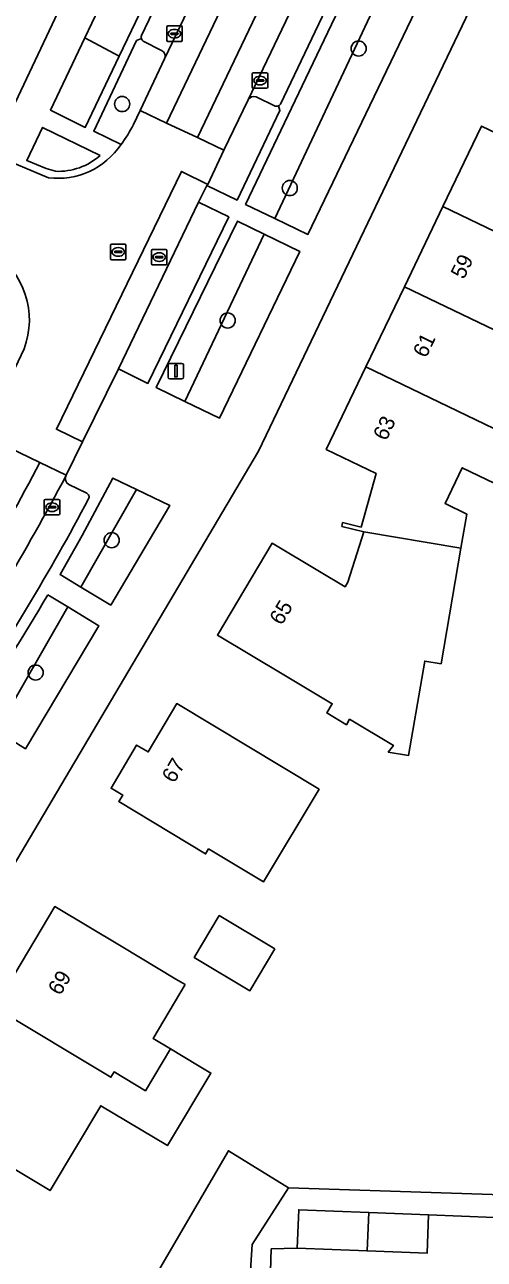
# Model space of a CAD drawing. Extents: x 161354 to 162026, y 386504 to 387460.
# Drawn here: x 161628.5 to 161658.2, y 386849.6 to 386929.5 of the extents above; entities that cross this region are included whole.
import ezdxf

# ---------------------------------------------------------------- set-up
doc = ezdxf.new("R2010")
doc.units = 0
for name, color, linetype in [('IMGEO_Boom', 7, 'Continuous'), ('IMGEO_Erf', 7, 'Continuous'), ('IMGEO_Groenvoorziening', 7, 'Continuous'), ('IMGEO_Kolk', 7, 'Continuous'), ('IMGEO_Lichtmast', 7, 'Continuous'), ('IMGEO_Pand', 7, 'Continuous'), ('IMGEO_Pand_nummerreeks', 7, 'Continuous'), ('IMGEO_Parkeervlak_open', 7, 'Continuous'), ('IMGEO_Rijbaan_lokaal_gesloten', 7, 'Continuous'), ('IMGEO_Rijbaan_lokaal_open', 7, 'Continuous'), ('IMGEO_Rioolput', 7, 'Continuous'), ('IMGEO_Voetpad_open', 7, 'Continuous')]:
    doc.layers.add(name, color=color, linetype=linetype)

msp = doc.modelspace()

# ---------------------------------------------------------------- linework, layer by layer
at = {"layer": 'IMGEO_Boom'}
for centre in [(161650.071, 386927.935), (161634.764, 386924.348), (161645.612, 386918.915), (161641.595, 386910.355), (161634.089, 386896.145), (161629.167, 386887.587)]:
    msp.add_circle(centre, 0.489, dxfattribs=at)
at = {"layer": 'IMGEO_Erf'}
for points in [[(161609.772, 386930.611), (161627.852, 386924.437), (161646.394, 386963.7)], [(161671.646, 386960.486), (161643.583, 386901.899), (161613.704, 386851.442), (161606.973, 386839.109)], [(161662.034, 386898.303), (161656.777, 386900.829), (161655.663, 386898.511), (161657.069, 386897.835), (161656.691, 386895.63), (161655.408, 386888.154), (161654.347, 386888.33), (161653.301, 386882.234), (161651.984, 386882.448), (161652.317, 386882.877), (161649.486, 386884.566), (161649.281, 386884.217), (161648.005, 386884.978), (161648.361, 386885.574), (161645.221, 386887.448), (161640.927, 386890.01), (161644.47, 386895.948), (161647.541, 386894.116), (161649.194, 386893.131), (161649.379, 386893.441), (161650.398, 386896.683), (161648.99, 386897.033), (161649.036, 386897.29), (161650.232, 386896.992), (161651.206, 386900.467), (161647.979, 386902.018), (161650.539, 386907.346), (161653.035, 386912.538), (161655.529, 386917.729), (161658.024, 386922.92), (161662.531, 386920.754)], [(161607.606, 386836.329), (161614.08, 386832.566), (161616.666, 386831.46), (161619.885, 386830.063), (161625.794, 386829.168), (161641.973, 386828.529), (161642.086, 386831.552), (161638.145, 386831.727), (161634.203, 386831.903), (161634.484, 386838.208), (161638.425, 386838.033), (161642.367, 386837.857), (161642.668, 386842.533), (161634.343, 386844.128), (161641.64, 386856.664), (161645.532, 386854.261), (161666.63, 386853.581)], [(161658.868, 386852.352), (161656.733, 386852.437), (161654.597, 386852.522), (161654.497, 386850.041), (161650.62, 386850.195), (161646.1, 386850.375), (161644.418, 386850.318), (161644.194, 386843.113), (161650.468, 386842.864), (161656.445, 386842.626), (161662.4, 386842.39)]]:
    msp.add_lwpolyline(points, dxfattribs=at)
for points in [[(161647.506, 386880.039), (161643.904, 386874.053), (161640.358, 386876.184), (161640.166, 386875.864), (161634.554, 386879.242), (161634.801, 386879.66), (161634.054, 386880.102), (161635.702, 386882.898), (161636.453, 386882.454), (161638.3, 386885.579)], [(161638.85, 386867.408), (161636.771, 386863.927), (161637.887, 386863.26), (161639.65, 386862.207), (161640.508, 386861.694), (161637.7, 386856.996), (161633.379, 386859.578), (161630.103, 386854.096), (161626.533, 386856.23), (161622.241, 386858.795), (161626.502, 386865.924), (161630.405, 386872.455), (161634.697, 386869.89), (161638.25, 386867.767)], [(161644.657, 386869.723), (161643.037, 386867.012), (161639.432, 386869.166), (161641.052, 386871.877)]]:
    msp.add_lwpolyline(points, close=True, dxfattribs=at)
at = {"layer": 'IMGEO_Groenvoorziening'}
for points in [[(161652.017, 386932.645), (161650.229, 386933.516), (161646.664, 386926.03), (161642.757, 386917.859), (161644.645, 386916.953)], [(161636.432, 386931.334), (161634.166, 386932.454), (161632.354, 386928.634), (161634.579, 386927.444)], [(161654.3, 386931.533), (161652.017, 386932.645), (161644.645, 386916.953), (161646.79, 386915.923)], [(161632.354, 386928.634), (161630.139, 386923.962), (161632.383, 386922.835), (161634.579, 386927.444)], [(161643.966, 386915.933), (161642.23, 386916.778), (161636.976, 386906.013), (161638.817, 386905.12)], [(161646.26, 386914.816), (161643.966, 386915.933), (161638.817, 386905.12), (161641.063, 386904.029)], [(161635.689, 386899.427), (161634.154, 386900.16), (161632.168, 386896.449), (161630.753, 386893.922), (161632.087, 386893.116)], [(161637.849, 386898.396), (161635.689, 386899.427), (161632.087, 386893.116), (161634.025, 386891.946)], [(161633.249, 386890.619), (161631.253, 386891.827), (161626.635, 386883.81), (161628.505, 386882.663)]]:
    msp.add_lwpolyline(points, close=True, dxfattribs=at)
for points in [[(161636.011, 386928.576), (161635.7, 386928.451), (161632.927, 386922.6), (161634.698, 386921.74)], [(161637.305, 386927.818), (161636.132, 386928.417)], [(161635.925, 386923.923), (161637.51, 386927.262)], [(161642.917, 386924.631), (161641.341, 386921.357), (161640.317, 386919.149), (161640.253, 386919.091), (161642.204, 386918.133), (161644.979, 386923.936), (161644.881, 386924.237)], [(161644.676, 386924.215), (161643.437, 386924.811)], [(161635.498, 386923.022), (161635.925, 386923.923)], [(161633.347, 386921.03), (161629.617, 386922.84), (161628.589, 386920.696)], [(161628.589, 386920.696), (161629.854, 386920.171), (161630.454, 386919.998)], [(161631.253, 386891.827), (161629.956, 386892.612)], [(161625.025, 386884.797), (161626.635, 386883.81), (161631.253, 386891.827)]]:
    msp.add_lwpolyline(points, dxfattribs=at)
for centre, radius, start, end in [((161636.286, 386928.66), 0.288, 196.9575, 237.58523), ((161637.133, 386927.439), 0.416, 334.85295, 65.62542), ((161643.303, 386924.356), 0.474, 73.59776, 144.58922), ((161644.744, 386924.547), 0.339, 258.40617, 293.84458), ((161627.063, 386927.395), 9.501, 323.47345, 332.59617), ((161630.631, 386924.072), 4.077, 267.50604, 311.75895), ((161490.613, 386975.069), 161.913, 326.11426, 329.38467)]:
    msp.add_arc(centre, radius, start, end, dxfattribs=at)
at = {"layer": 'IMGEO_Kolk'}
for p, q in [((161637.65, 386928.471), (161637.65, 386929.323)), ((161637.725, 386929.397), (161638.577, 386929.397)), ((161638.138, 386929.177), (161638.163, 386929.177)), ((161638.651, 386929.323), (161638.651, 386928.471)), ((161638.577, 386928.397), (161637.725, 386928.397)), ((161637.909, 386928.891), (161637.909, 386928.903)), ((161638.347, 386928.854), (161637.949, 386928.854)), ((161637.952, 386928.94), (161638.35, 386928.94)), ((161638.161, 386928.617), (161638.136, 386928.617)), ((161638.393, 386928.903), (161638.393, 386928.891)), ((161643.189, 386925.443), (161643.189, 386926.295)), ((161643.264, 386926.369), (161644.116, 386926.369)), ((161643.491, 386925.912), (161643.889, 386925.912)), ((161643.677, 386926.149), (161643.702, 386926.149)), ((161644.19, 386926.295), (161644.19, 386925.443)), ((161644.116, 386925.369), (161643.264, 386925.369)), ((161643.448, 386925.863), (161643.448, 386925.875)), ((161643.886, 386925.826), (161643.488, 386925.826)), ((161643.7, 386925.589), (161643.675, 386925.589)), ((161643.932, 386925.875), (161643.932, 386925.863)), ((161629.802, 386898.78), (161630.654, 386898.78)), ((161629.727, 386897.854), (161629.727, 386898.706)), ((161629.986, 386898.274), (161629.986, 386898.286)), ((161630.424, 386898.237), (161630.026, 386898.237)), ((161630.029, 386898.323), (161630.427, 386898.323)), ((161630.238, 386898), (161630.213, 386898)), ((161630.215, 386898.56), (161630.24, 386898.56)), ((161630.47, 386898.286), (161630.47, 386898.274)), ((161630.728, 386898.706), (161630.728, 386897.854)), ((161630.654, 386897.78), (161629.802, 386897.78))]:
    msp.add_line(p, q, dxfattribs=at)
for points in [[(161637.65, 386928.471), (161637.65, 386929.323)], [(161637.725, 386929.397), (161638.577, 386929.397)], [(161638.651, 386929.323), (161638.651, 386928.471)], [(161638.577, 386928.397), (161637.725, 386928.397)], [(161643.189, 386925.443), (161643.189, 386926.295)], [(161643.264, 386926.369), (161644.116, 386926.369)], [(161644.19, 386926.295), (161644.19, 386925.443)], [(161644.116, 386925.369), (161643.264, 386925.369)], [(161629.802, 386898.78), (161630.654, 386898.78)], [(161629.727, 386897.854), (161629.727, 386898.706)], [(161630.728, 386898.706), (161630.728, 386897.854)], [(161630.654, 386897.78), (161629.802, 386897.78)]]:
    msp.add_lwpolyline(points, dxfattribs=at)
for centre, radius, start, end in [((161637.727, 386929.321), 0.0765, 91.55205, 178.44795), ((161637.727, 386929.321), 0.0765, 91.55205, 178.44795), ((161638.575, 386929.321), 0.0765, 1.55205, 88.44795), ((161638.575, 386929.321), 0.0765, 1.55205, 88.44795), ((161637.727, 386928.473), 0.0765, 181.55205, 268.44795), ((161637.727, 386928.473), 0.0765, 181.55205, 268.44795), ((161637.949, 386928.9), 0.0403, 85.87752, 175.75265), ((161637.946, 386928.89), 0.0366, 178.93798, 274.71019), ((161638.35, 386928.897), 0.043, 264.86636, 352.45326), ((161638.354, 386928.902), 0.0386, 1.73085, 96.63898), ((161638.575, 386928.473), 0.0765, 271.55205, 358.44795), ((161638.575, 386928.473), 0.0765, 271.55205, 358.44795), ((161643.266, 386926.293), 0.0765, 91.55205, 178.44795), ((161643.266, 386926.293), 0.0765, 91.55205, 178.44795), ((161643.488, 386925.872), 0.0403, 85.87752, 175.75265), ((161643.893, 386925.874), 0.0386, 1.73085, 96.63898), ((161644.114, 386926.293), 0.0765, 1.55205, 88.44795), ((161644.114, 386926.293), 0.0765, 1.55205, 88.44795), ((161643.266, 386925.445), 0.0765, 181.55205, 268.44795), ((161643.266, 386925.445), 0.0765, 181.55205, 268.44795), ((161643.485, 386925.862), 0.0366, 178.93798, 274.71019), ((161643.889, 386925.869), 0.043, 264.86636, 352.45326), ((161644.114, 386925.445), 0.0765, 271.55205, 358.44795), ((161644.114, 386925.445), 0.0765, 271.55205, 358.44795), ((161629.804, 386898.704), 0.0765, 91.55205, 178.44795), ((161629.804, 386898.704), 0.0765, 91.55205, 178.44795), ((161630.652, 386898.704), 0.0765, 1.55205, 88.44795), ((161630.652, 386898.704), 0.0765, 1.55205, 88.44795), ((161630.026, 386898.283), 0.0403, 85.87752, 175.75265), ((161630.023, 386898.273), 0.0366, 178.93798, 274.71019), ((161630.427, 386898.28), 0.043, 264.86636, 352.45326), ((161630.431, 386898.285), 0.0386, 1.73085, 96.63898), ((161629.804, 386897.856), 0.0765, 181.55205, 268.44795), ((161629.804, 386897.856), 0.0765, 181.55205, 268.44795), ((161630.652, 386897.856), 0.0765, 271.55205, 358.44795), ((161630.652, 386897.856), 0.0765, 271.55205, 358.44795)]:
    msp.add_arc(centre, radius, start, end, dxfattribs=at)
for centre, major_axis, ratio, start_param, end_param in [((161638.137, 386928.897), (-0.387, 0.002), 0.722429, 4.712389, 7.853982), ((161638.162, 386928.897), (-0.39, 0.002), 0.717154, 1.570796, 4.712389), ((161643.676, 386925.869), (-0.387, 0.002), 0.722429, 4.712389, 7.853982), ((161643.701, 386925.869), (-0.39, 0.002), 0.717154, 1.570796, 4.712389), ((161630.214, 386898.28), (-0.387, 0.002), 0.722429, 4.712389, 7.853982), ((161630.239, 386898.28), (-0.39, 0.002), 0.717154, 1.570796, 4.712389)]:
    msp.add_ellipse(centre, major_axis=major_axis, ratio=ratio, start_param=start_param, end_param=end_param, dxfattribs=at)
at = {"layer": 'IMGEO_Lichtmast'}
for p, q in [((161637.847, 386907.579), (161638.637, 386907.579)), ((161638.637, 386907.579), (161637.847, 386907.579)), ((161637.747, 386906.679), (161637.747, 386907.479)), ((161637.747, 386907.479), (161637.747, 386906.679)), ((161638.737, 386907.479), (161638.737, 386906.679)), ((161638.737, 386906.679), (161638.737, 386907.479)), ((161638.637, 386906.579), (161637.847, 386906.579)), ((161637.847, 386906.579), (161638.637, 386906.579))]:
    msp.add_line(p, q, dxfattribs=at)
msp.add_lwpolyline([(161638.167, 386907.454), (161638.317, 386907.454), (161638.317, 386906.704), (161638.167, 386906.704), (161638.167, 386907.454)], dxfattribs=at)
for centre, start, end in [((161637.847, 386907.479), 90, 180), ((161637.847, 386907.479), 90, 180), ((161638.637, 386907.479), 0, 90), ((161638.637, 386907.479), 360, 90), ((161637.847, 386906.679), 180, 270), ((161637.847, 386906.679), 180, 270), ((161638.637, 386906.679), 270, 0), ((161638.637, 386906.679), 270, 0)]:
    msp.add_arc(centre, 0.1, start, end, dxfattribs=at)
at = {"layer": 'IMGEO_Pand'}
for points in [[(161666.552, 386916.092), (161667.619, 386918.309), (161666.003, 386919.086), (161662.531, 386920.754), (161658.024, 386922.92), (161655.529, 386917.729), (161667.953, 386911.758), (161671.703, 386910.095), (161673.808, 386909.162), (161673.944, 386909.444), (161674.115, 386909.362), (161674.884, 386910.962), (161673.53, 386911.613), (161673.959, 386912.504)], [(161667.953, 386911.758), (161655.529, 386917.729), (161653.035, 386912.538), (161661.001, 386908.709), (161662.248, 386911.305), (161666.867, 386909.031), (161666.627, 386908.543), (161670.128, 386906.819), (161670.364, 386907.309), (161670.387, 386907.356), (161670.821, 386908.26), (161671.703, 386910.095)], [(161659.915, 386906.45), (161661.001, 386908.709), (161653.035, 386912.538), (161650.539, 386907.346), (161662.985, 386901.364), (161663.411, 386901.166), (161664.69, 386903.828), (161664.817, 386904.094)], [(161663.411, 386901.166), (161662.985, 386901.364), (161650.539, 386907.346), (161647.979, 386902.018), (161651.206, 386900.467), (161650.232, 386896.992), (161649.036, 386897.29), (161648.99, 386897.033), (161650.398, 386896.683), (161656.691, 386895.63), (161657.069, 386897.835), (161655.663, 386898.511), (161656.777, 386900.829), (161662.034, 386898.303), (161662.155, 386898.553), (161662.359, 386898.977)], [(161656.691, 386895.63), (161650.398, 386896.683), (161649.379, 386893.441), (161649.194, 386893.131), (161647.541, 386894.116), (161644.47, 386895.948), (161640.927, 386890.01), (161645.221, 386887.448), (161648.361, 386885.574), (161648.005, 386884.978), (161649.281, 386884.217), (161649.486, 386884.566), (161652.317, 386882.877), (161651.984, 386882.448), (161653.301, 386882.234), (161654.347, 386888.33), (161655.408, 386888.154)], [(161636.453, 386882.454), (161635.702, 386882.898), (161634.054, 386880.102), (161634.801, 386879.66), (161634.554, 386879.242), (161640.166, 386875.864), (161640.358, 386876.184), (161643.904, 386874.053), (161647.506, 386880.039), (161638.3, 386885.579)], [(161638.85, 386867.408), (161638.25, 386867.767), (161634.697, 386869.89), (161630.405, 386872.455), (161626.502, 386865.924), (161634.037, 386861.419), (161634.242, 386861.762), (161636.267, 386860.551), (161637.887, 386863.26), (161636.771, 386863.927)], [(161644.657, 386869.723), (161641.052, 386871.877), (161639.432, 386869.166), (161643.037, 386867.012)], [(161626.502, 386865.924), (161622.241, 386858.795), (161626.533, 386856.23), (161630.103, 386854.096), (161633.379, 386859.578), (161637.7, 386856.996), (161640.508, 386861.694), (161639.65, 386862.207), (161637.887, 386863.26), (161636.267, 386860.551), (161634.242, 386861.762), (161634.037, 386861.419)], [(161645.532, 386854.261), (161641.64, 386856.664), (161634.343, 386844.128), (161642.668, 386842.533), (161643.19, 386850.602)], [(161650.72, 386852.676), (161646.198, 386852.856), (161646.1, 386850.375), (161650.62, 386850.195)], [(161654.597, 386852.522), (161650.72, 386852.676), (161650.62, 386850.195), (161654.497, 386850.041)]]:
    msp.add_lwpolyline(points, close=True, dxfattribs=at)
at = {"layer": 'IMGEO_Parkeervlak_open'}
for points in [[(161653.421, 386960.496), (161651.637, 386961.362), (161636.021, 386928.775)], [(161637.51, 386927.262), (161653.421, 386960.496)], [(161658.053, 386951.639), (161656.28, 386952.508), (161642.917, 386924.631)], [(161645.018, 386924.348), (161658.053, 386951.639)], [(161636.132, 386928.417), (161637.305, 386927.818)], [(161643.437, 386924.811), (161644.676, 386924.215)], [(161632.47, 386899.18), (161631.319, 386899.754)]]:
    msp.add_lwpolyline(points, dxfattribs=at)
msp.add_lwpolyline([(161639.708, 386918), (161634.524, 386907.228), (161636.431, 386906.285), (161641.662, 386917.047)], close=True, dxfattribs=at)
for centre, radius, start, end in [((161636.282, 386928.662), 0.285, 156.6372, 197.60927), ((161636.286, 386928.66), 0.288, 196.9575, 237.58523), ((161637.133, 386927.439), 0.416, 334.85295, 65.62542), ((161643.303, 386924.356), 0.474, 73.59776, 144.58922), ((161644.751, 386924.537), 0.327, 293.38172, 324.64838), ((161644.744, 386924.547), 0.339, 258.40617, 293.84458), ((161494.394, 386972.85), 154.789, 325.94983, 332.04142), ((161631.491, 386900.122), 0.406, 157.0909, 244.92572), ((161506.276, 386965.708), 142.935, 325.66388, 332.09614), ((161632.355, 386898.938), 0.268, 332.78729, 64.55418)]:
    msp.add_arc(centre, radius, start, end, dxfattribs=at)
at = {"layer": 'IMGEO_Rijbaan_lokaal_gesloten'}
for points in [[(161657.516, 386964.711), (161655.829, 386965.562), (161653.421, 386960.496), (161637.51, 386927.262), (161635.925, 386923.923), (161637.626, 386923.117)], [(161656.28, 386952.508), (161658.715, 386957.622), (161661.265, 386962.944), (161659.528, 386963.762), (161639.641, 386922.189), (161641.341, 386921.357), (161642.917, 386924.631)], [(161639.708, 386918), (161640.253, 386919.091), (161640.317, 386919.149), (161638.615, 386919.995), (161630.512, 386903.319), (161632.194, 386902.501), (161634.524, 386907.228)]]:
    msp.add_lwpolyline(points, close=True, dxfattribs=at)
msp.add_lwpolyline([(161631.117, 386900.28), (161631.15, 386900.341), (161629.437, 386901.161)], dxfattribs=at)
for centre, radius, start, end in [((161502.557, 386967.817), 143.323, 325.75385, 332.28494), ((161494.394, 386972.85), 154.789, 325.94983, 332.04142)]:
    msp.add_arc(centre, radius, start, end, dxfattribs=at)
at = {"layer": 'IMGEO_Rijbaan_lokaal_open'}
msp.add_lwpolyline([(161659.528, 386963.762), (161657.516, 386964.711), (161637.626, 386923.117), (161639.641, 386922.189)], close=True, dxfattribs=at)
for points in [[(161640.317, 386919.149), (161641.341, 386921.357), (161639.641, 386922.189), (161637.626, 386923.117), (161635.925, 386923.923), (161635.498, 386923.022)], [(161629.99, 386919.584), (161626.509, 386921.053), (161624.541, 386915.869), (161626.684, 386914.559)], [(161628.236, 386908.1), (161626.801, 386905.161), (161625.799, 386903.114), (161625.763, 386903.031), (161625.741, 386902.981), (161627.425, 386902.148), (161629.437, 386901.161), (161631.15, 386900.341), (161632.194, 386902.501), (161630.512, 386903.319), (161638.615, 386919.995), (161640.317, 386919.149)], [(161629.437, 386901.161), (161627.425, 386902.148)]]:
    msp.add_lwpolyline(points, dxfattribs=at)
for centre, radius, start, end in [((161627.063, 386927.395), 9.501, 323.47345, 332.59617), ((161630.594, 386924.484), 4.937, 262.97656, 326.23369), ((161623.529, 386910.385), 5.232, 334.10752, 52.91481), ((161502.557, 386967.817), 143.323, 325.75385, 332.28494)]:
    msp.add_arc(centre, radius, start, end, dxfattribs=at)
at = {"layer": 'IMGEO_Rioolput'}
for p, q in [((161634.013, 386914.359), (161634.013, 386915.211)), ((161634.088, 386915.285), (161634.94, 386915.285)), ((161634.272, 386914.779), (161634.272, 386914.791)), ((161634.71, 386914.742), (161634.312, 386914.742)), ((161634.315, 386914.828), (161634.713, 386914.828)), ((161634.501, 386915.065), (161634.526, 386915.065)), ((161634.756, 386914.791), (161634.756, 386914.779)), ((161635.014, 386915.211), (161635.014, 386914.359)), ((161636.664, 386914.024), (161636.664, 386914.876)), ((161636.739, 386914.95), (161637.591, 386914.95)), ((161637.152, 386914.73), (161637.177, 386914.73)), ((161637.665, 386914.876), (161637.665, 386914.024)), ((161634.94, 386914.285), (161634.088, 386914.285)), ((161634.524, 386914.505), (161634.499, 386914.505)), ((161637.591, 386913.95), (161636.739, 386913.95)), ((161636.923, 386914.444), (161636.923, 386914.456)), ((161637.361, 386914.407), (161636.963, 386914.407)), ((161636.966, 386914.493), (161637.364, 386914.493)), ((161637.175, 386914.17), (161637.15, 386914.17)), ((161637.407, 386914.456), (161637.407, 386914.444))]:
    msp.add_line(p, q, dxfattribs=at)
for points in [[(161634.013, 386914.359), (161634.013, 386915.211)], [(161634.088, 386915.285), (161634.94, 386915.285)], [(161635.014, 386915.211), (161635.014, 386914.359)], [(161636.664, 386914.024), (161636.664, 386914.876)], [(161636.739, 386914.95), (161637.591, 386914.95)], [(161637.665, 386914.876), (161637.665, 386914.024)], [(161634.94, 386914.285), (161634.088, 386914.285)], [(161637.591, 386913.95), (161636.739, 386913.95)]]:
    msp.add_lwpolyline(points, dxfattribs=at)
for centre, radius, start, end in [((161634.09, 386915.209), 0.0765, 91.55205, 178.44795), ((161634.09, 386915.209), 0.0765, 91.55205, 178.44795), ((161634.312, 386914.788), 0.0403, 85.87752, 175.75265), ((161634.309, 386914.778), 0.0366, 178.93798, 274.71019), ((161634.713, 386914.785), 0.043, 264.86636, 352.45326), ((161634.717, 386914.79), 0.0386, 1.73085, 96.63898), ((161634.938, 386915.209), 0.0765, 1.55205, 88.44795), ((161634.938, 386915.209), 0.0765, 1.55205, 88.44795), ((161636.741, 386914.874), 0.0765, 91.55205, 178.44795), ((161636.741, 386914.874), 0.0765, 91.55205, 178.44795), ((161637.589, 386914.874), 0.0765, 1.55205, 88.44795), ((161637.589, 386914.874), 0.0765, 1.55205, 88.44795), ((161634.09, 386914.361), 0.0765, 181.55205, 268.44795), ((161634.09, 386914.361), 0.0765, 181.55205, 268.44795), ((161634.938, 386914.361), 0.0765, 271.55205, 358.44795), ((161634.938, 386914.361), 0.0765, 271.55205, 358.44795), ((161636.741, 386914.026), 0.0765, 181.55205, 268.44795), ((161636.741, 386914.026), 0.0765, 181.55205, 268.44795), ((161636.963, 386914.453), 0.0403, 85.87752, 175.75265), ((161636.96, 386914.443), 0.0366, 178.93798, 274.71019), ((161637.364, 386914.45), 0.043, 264.86636, 352.45326), ((161637.368, 386914.455), 0.0386, 1.73085, 96.63898), ((161637.589, 386914.026), 0.0765, 271.55205, 358.44795), ((161637.589, 386914.026), 0.0765, 271.55205, 358.44795)]:
    msp.add_arc(centre, radius, start, end, dxfattribs=at)
for centre, major_axis, ratio, start_param, end_param in [((161634.5, 386914.785), (-0.387, 0.002), 0.722429, 4.712389, 7.853982), ((161634.525, 386914.785), (-0.39, 0.002), 0.717154, 1.570796, 4.712389), ((161637.151, 386914.45), (-0.387, 0.002), 0.722429, 4.712389, 7.853982), ((161637.176, 386914.45), (-0.39, 0.002), 0.717154, 1.570796, 4.712389)]:
    msp.add_ellipse(centre, major_axis=major_axis, ratio=ratio, start_param=start_param, end_param=end_param, dxfattribs=at)
at = {"layer": 'IMGEO_Voetpad_open'}
for points in [[(161651.637, 386961.362), (161650.919, 386961.618), (161648.475, 386956.529), (161647.467, 386954.43), (161645.167, 386955.52), (161646.203, 386957.692), (161648.603, 386962.721), (161646.394, 386963.7), (161627.852, 386924.437), (161626.509, 386921.053), (161629.99, 386919.584)], [(161636.021, 386928.775), (161651.637, 386961.362)], [(161662.748, 386961.434), (161660.499, 386956.76), (161658.053, 386951.639), (161645.018, 386924.348)], [(161606.973, 386839.109), (161613.704, 386851.442), (161643.583, 386901.899), (161671.646, 386960.486)], [(161634.698, 386921.74), (161632.927, 386922.6), (161635.7, 386928.451), (161636.011, 386928.576)], [(161644.881, 386924.237), (161644.979, 386923.936), (161642.204, 386918.133), (161640.253, 386919.091), (161639.708, 386918), (161641.662, 386917.047), (161636.431, 386906.285), (161634.524, 386907.228), (161632.194, 386902.501), (161631.15, 386900.341), (161631.117, 386900.28)], [(161630.454, 386919.998), (161629.854, 386920.171), (161628.589, 386920.696), (161629.617, 386922.84), (161633.347, 386921.03)], [(161631.319, 386899.754), (161632.47, 386899.18)], [(161629.956, 386892.612), (161631.253, 386891.827), (161633.249, 386890.619), (161628.505, 386882.663), (161626.635, 386883.81), (161625.025, 386884.797)], [(161666.63, 386853.581), (161645.532, 386854.261), (161643.19, 386850.602), (161642.668, 386842.533), (161642.367, 386837.857), (161642.086, 386831.552), (161641.973, 386828.529), (161643.629, 386828.464), (161643.854, 386834.56), (161644.053, 386839.557), (161644.194, 386843.113), (161644.418, 386850.318), (161646.1, 386850.375), (161646.198, 386852.856), (161650.72, 386852.676), (161654.597, 386852.522), (161656.733, 386852.437), (161658.868, 386852.352)]]:
    msp.add_lwpolyline(points, dxfattribs=at)
for points in [[(161650.229, 386933.516), (161652.017, 386932.645), (161654.3, 386931.533), (161646.79, 386915.923), (161644.645, 386916.953), (161642.757, 386917.859), (161646.664, 386926.03)], [(161636.432, 386931.334), (161634.579, 386927.444), (161632.383, 386922.835), (161630.139, 386923.962), (161632.354, 386928.634), (161634.166, 386932.454)], [(161642.23, 386916.778), (161643.966, 386915.933), (161646.26, 386914.816), (161641.063, 386904.029), (161638.817, 386905.12), (161636.976, 386906.013)], [(161634.154, 386900.16), (161635.689, 386899.427), (161637.849, 386898.396), (161634.025, 386891.946), (161632.087, 386893.116), (161630.753, 386893.922), (161632.168, 386896.449)]]:
    msp.add_lwpolyline(points, close=True, dxfattribs=at)
for centre, radius, start, end in [((161636.282, 386928.662), 0.285, 156.6372, 197.60927), ((161644.751, 386924.537), 0.327, 293.38172, 324.64838), ((161630.594, 386924.484), 4.937, 262.97656, 326.23369), ((161630.631, 386924.072), 4.077, 267.50604, 311.75895), ((161623.529, 386910.385), 5.232, 334.10752, 52.91481), ((161631.491, 386900.122), 0.406, 157.0909, 244.92572), ((161506.276, 386965.708), 142.935, 325.66388, 332.09614), ((161632.355, 386898.938), 0.268, 332.78729, 64.55418), ((161490.613, 386975.069), 161.913, 326.11426, 329.38467)]:
    msp.add_arc(centre, radius, start, end, dxfattribs=at)

# ---------------------------------------------------------------- texts
at = {"layer": 'IMGEO_Pand_nummerreeks'}
for s, rotation, p in [('59', 64.3317, (161656.881, 386912.967)), ('61', 64.3317, (161654.435, 386907.878)), ('63', 64.3317, (161651.858, 386902.516)), ('65', 59.17508, (161645.092, 386890.589)), ('67', 59.41572, (161638.13, 386880.379)), ('69', 59.13497, (161630.755, 386866.647))]:
    msp.add_text(s, height=1, rotation=rotation, dxfattribs=at).set_placement(p)

doc.saveas('drawing.dxf')
